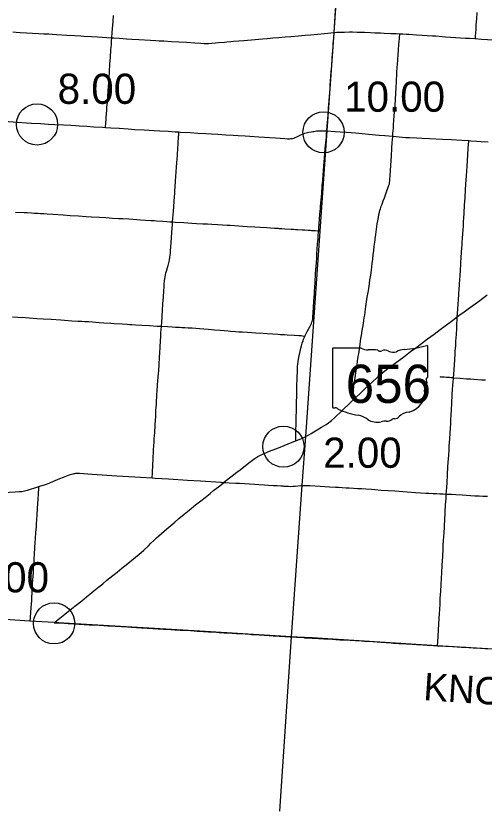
# Model space of a CAD drawing. Extents: x 1813937 to 1948437, y 826606 to 1022856.
# Drawn here: x 1890191 to 1907255, y 849557 to 878544 of the extents above; entities that cross this region are included whole.
import ezdxf

# ---------------------------------------------------------------- set-up
doc = ezdxf.new("R2010")
doc.units = 0
for name, color, linetype in [('Default', 7, 'Continuous'), ('GM_X_Adjacent_County', 7, 'Continuous'), ('GM_X_Adjacent_County_Text', 7, 'Continuous'), ('GM_X_County', 7, 'Continuous'), ('GM_X_County_Road', 7, 'Continuous'), ('GM_X_State_Route', 7, 'Continuous'), ('GM_X_State_Shield', 7, 'Continuous'), ('GM_X_Township', 7, 'Continuous'), ('GM_X_Township_Road', 7, 'Continuous')]:
    doc.layers.add(name, color=color, linetype=linetype)

msp = doc.modelspace()

# ---------------------------------------------------------------- linework, layer by layer
at = {"layer": 'Default'}
for centre in [(1890962, 874588), (1901403, 874300), (1899943, 862842), (1891585, 856400)]:
    msp.add_circle(centre, 750, dxfattribs=at)
at = {"layer": 'GM_X_Adjacent_County'}
msp.add_line((1900228, 855908), (1899800, 849557), dxfattribs=at)
at = {"layer": 'GM_X_County'}
msp.add_lwpolyline([(1909640, 855342), (1905546, 855583), (1900992, 855867), (1900447, 855895), (1900228, 855908), (1896895, 856116), (1891937, 856405), (1891588, 856432), (1890695, 856480), (1886895, 856734)], dxfattribs=at)
at = {"layer": 'GM_X_County_Road'}
for points in [[(1901788, 877939), (1901801, 878159), (1901811, 878322), (1901825, 878552), (1901847, 878896), (1901869, 879256), (1901894, 879616), (1901903, 879780), (1901914, 879927), (1901928, 880124), (1901938, 880255), (1901953, 880500), (1901979, 880877), (1901991, 881073), (1902003, 881270), (1902016, 881499), (1902024, 881630), (1902038, 881827), (1902052, 882023), (1902064, 882205)], [(1901526, 874352), (1901541, 874540), (1901560, 874771), (1901575, 874967), (1901585, 875124), (1901590, 875197), (1901597, 875311), (1901620, 875605), (1901640, 875884), (1901650, 876015), (1901672, 876326), (1901686, 876522), (1901701, 876718), (1901721, 876997), (1901743, 877291), (1901752, 877406), (1901760, 877537), (1901773, 877733), (1901788, 877939)], [(1906279, 867576), (1906289, 867687), (1906301, 867867), (1906324, 868201), (1906336, 868382), (1906351, 868620), (1906357, 868701), (1906361, 868767), (1906372, 868930), (1906382, 869077), (1906392, 869258), (1906397, 869339), (1906403, 869437), (1906409, 869536), (1906424, 869748), (1906435, 869912), (1906448, 870108), (1906452, 870174), (1906461, 870304), (1906470, 870435), (1906482, 870615), (1906491, 870746), (1906500, 870893), (1906508, 871057), (1906514, 871155), (1906524, 871368), (1906542, 871647), (1906561, 871908), (1906582, 872219), (1906606, 872579), (1906614, 872694), (1906628, 872906), (1906638, 873054), (1906653, 873283), (1906665, 873463), (1906679, 873725), (1906688, 873859), (1906695, 873970), (1906696, 873998)], [(1906139, 865355), (1906148, 865479), (1906161, 865659), (1906173, 865815), (1906185, 866019), (1906199, 866231), (1906205, 866329), (1906219, 866526), (1906230, 866675), (1906238, 866822), (1906244, 866918), (1906256, 867164), (1906266, 867327), (1906272, 867458), (1906276, 867540), (1906279, 867576)], [(1905878, 861113), (1905895, 861355), (1905906, 861535), (1905921, 861797), (1905939, 862119), (1905957, 862403), (1905965, 862534), (1905977, 862730), (1905986, 862861), (1905993, 862992), (1906002, 863123), (1906029, 863532), (1906038, 863679), (1906046, 863827), (1906056, 864007), (1906068, 864187), (1906081, 864432), (1906084, 864514), (1906092, 864645), (1906097, 864743), (1906108, 864923), (1906119, 865070), (1906129, 865201), (1906138, 865332), (1906139, 865355)], [(1891033, 861391), (1891103, 861412), (1891228, 861451), (1891306, 861477), (1891367, 861499), (1891427, 861524), (1891533, 861569), (1891790, 861677), (1891927, 861733), (1892050, 861779), (1892174, 861823), (1892221, 861838), (1892284, 861856), (1892317, 861863), (1892340, 861867), (1892376, 861873), (1892414, 861874), (1892457, 861874), (1892511, 861873), (1892657, 861863), (1892975, 861844), (1893875, 861784), (1894530, 861742), (1894727, 861729), (1895156, 861701)], [(1895156, 861701), (1895267, 861694), (1895758, 861664), (1896445, 861620), (1896920, 861591), (1897657, 861542), (1897691, 861539), (1897763, 861534)], [(1897763, 861534), (1897839, 861530), (1897960, 861524), (1898208, 861515), (1898338, 861507), (1898526, 861493), (1898704, 861483), (1898895, 861472), (1899045, 861464), (1899246, 861452), (1899400, 861441), (1899581, 861430), (1899712, 861422), (1899842, 861413), (1899917, 861408)], [(1889657, 861171), (1889692, 861173), (1889953, 861185), (1890166, 861196), (1890328, 861205), (1890402, 861211), (1890451, 861216), (1890507, 861229), (1890555, 861240), (1890618, 861258), (1890993, 861378), (1891033, 861391)], [(1899917, 861408), (1899957, 861406), (1900023, 861403), (1900085, 861399)], [(1900085, 861399), (1900121, 861397), (1900203, 861395), (1900285, 861397), (1900367, 861402), (1900580, 861425), (1900581, 861425)], [(1900581, 861425), (1900655, 861430), (1900723, 861431), (1900792, 861429), (1900906, 861425), (1901275, 861404), (1901620, 861382), (1901838, 861371), (1901949, 861365), (1902082, 861356), (1902229, 861346), (1902336, 861340), (1902491, 861330), (1902642, 861318), (1902782, 861311), (1902943, 861304), (1903156, 861289), (1903274, 861276), (1903498, 861259), (1903761, 861241), (1903998, 861229), (1904157, 861221), (1904294, 861213), (1904450, 861200), (1904752, 861174), (1904940, 861161), (1905132, 861150), (1905237, 861146), (1905393, 861139), (1905528, 861131), (1905646, 861126), (1905759, 861120), (1905878, 861113)], [(1905558, 855587), (1905569, 855740), (1905581, 855920), (1905607, 856378), (1905629, 856755), (1905638, 856902), (1905649, 857098), (1905659, 857311), (1905673, 857573), (1905685, 857803), (1905701, 858048), (1905712, 858247), (1905728, 858523), (1905746, 858834), (1905761, 859112), (1905769, 859243), (1905779, 859424), (1905789, 859571), (1905796, 859718), (1905807, 859898), (1905828, 860242), (1905835, 860356), (1905841, 860471), (1905854, 860717), (1905867, 860946), (1905878, 861110), (1905878, 861113)], [(1905878, 861113), (1905907, 861112), (1906070, 861106), (1906219, 861099), (1906460, 861085), (1906607, 861075), (1906762, 861065), (1906918, 861053), (1907080, 861046), (1907206, 861041), (1907376, 861036)], [(1891583, 856425), (1891639, 856423), (1891746, 856417), (1891965, 856405)], [(1891965, 856405), (1892090, 856398), (1892301, 856385), (1892481, 856374), (1892856, 856351), (1893019, 856342), (1893232, 856329), (1893543, 856312), (1893805, 856297), (1893879, 856293), (1894034, 856284), (1894263, 856272), (1894410, 856264), (1894495, 856259)], [(1894495, 856259), (1894590, 856253), (1894770, 856241), (1894983, 856228), (1895376, 856205), (1895572, 856194), (1895703, 856186), (1895981, 856169), (1896095, 856161), (1896177, 856156), (1896242, 856153), (1896308, 856149), (1896553, 856136), (1896684, 856128), (1896799, 856122), (1896913, 856115), (1896923, 856115)], [(1896923, 856115), (1897028, 856108), (1897142, 856101), (1897208, 856097), (1897503, 856079), (1897601, 856072), (1897699, 856066), (1897780, 856061), (1897911, 856054), (1898222, 856035), (1898370, 856027), (1898550, 856015), (1898713, 856004), (1898778, 856000), (1898893, 855993), (1899057, 855983), (1899416, 855960), (1899563, 855950), (1899678, 855942), (1899792, 855935), (1899988, 855922), (1900186, 855910)], [(1900186, 855910), (1900418, 855898), (1900516, 855892), (1900679, 855880), (1900711, 855878), (1900792, 855875), (1900873, 855872), (1900987, 855865), (1901117, 855858), (1901216, 855852), (1901412, 855841), (1901477, 855838), (1901559, 855834), (1901730, 855823), (1901855, 855815), (1902001, 855805), (1902166, 855796), (1902566, 855776), (1902784, 855762), (1902899, 855755), (1903029, 855748), (1903195, 855737), (1903359, 855726), (1903490, 855716), (1903572, 855710), (1903686, 855702), (1903866, 855689), (1903948, 855683), (1904151, 855671), (1904291, 855661), (1904422, 855654), (1904635, 855643), (1904787, 855633), (1904900, 855626), (1905019, 855619), (1905109, 855614), (1905174, 855610), (1905275, 855603), (1905405, 855595), (1905488, 855590), (1905558, 855587)]]:
    msp.add_lwpolyline(points, dxfattribs=at)
at = {"layer": 'GM_X_State_Route'}
for points in [[(1889758, 874704), (1890249, 874670), (1890576, 874650), (1890756, 874639), (1891084, 874620), (1891379, 874602), (1891608, 874588), (1891936, 874570), (1892198, 874556), (1892362, 874545), (1892493, 874537), (1892771, 874520), (1893033, 874504), (1893344, 874485), (1893457, 874478), (1893655, 874466), (1893950, 874446), (1894278, 874425), (1894523, 874409), (1894867, 874390), (1895227, 874371), (1895440, 874359), (1895735, 874340), (1895999, 874324), (1896130, 874316), (1896194, 874311), (1896545, 874289), (1896816, 874273), (1897111, 874256), (1897318, 874243), (1897553, 874228), (1897848, 874210), (1898110, 874195), (1898295, 874184), (1898552, 874168), (1898716, 874157), (1899043, 874137), (1899649, 874101), (1899993, 874075), (1900091, 874069), (1900157, 874068), (1900207, 874070), (1900240, 874073), (1900272, 874079), (1900320, 874091), (1900367, 874108), (1900428, 874133), (1900576, 874203), (1900666, 874244), (1900727, 874268), (1900773, 874283), (1900820, 874296), (1900868, 874306), (1900948, 874320), (1901007, 874330), (1901046, 874336), (1901092, 874342), (1901155, 874349), (1901230, 874356), (1901307, 874358), (1901372, 874358), (1901479, 874355), (1901526, 874352), (1901827, 874333), (1902007, 874320), (1902236, 874305), (1902416, 874291), (1902563, 874278), (1902808, 874257), (1903037, 874237), (1903429, 874202), (1903641, 874181), (1903918, 874156), (1903926, 874155), (1904277, 874122), (1904408, 874113), (1904539, 874106), (1904801, 874094), (1904997, 874087), (1905259, 874074), (1905735, 874054), (1906062, 874039), (1906439, 874017), (1906696, 873998), (1906766, 873993), (1906995, 873980), (1907143, 873972), (1907404, 873956)], [(1891583, 856425), (1891666, 856492), (1891977, 856734), (1892233, 856938), (1892386, 857062), (1892590, 857227), (1892769, 857371), (1892883, 857465), (1893036, 857588), (1893214, 857733), (1893354, 857847), (1893507, 857970), (1893725, 858144), (1893878, 858268), (1894056, 858412), (1894208, 858537), (1894474, 858756), (1894751, 858988), (1894850, 859074), (1895018, 859229), (1895114, 859320), (1895219, 859423), (1895313, 859515), (1895397, 859593), (1895495, 859680), (1895694, 859850), (1895983, 860092), (1896133, 860220), (1896321, 860378), (1896502, 860529), (1896742, 860718), (1896934, 860871), (1897088, 860994), (1897266, 861138), (1897408, 861250), (1897574, 861383), (1897740, 861517), (1897763, 861534), (1897869, 861618), (1898025, 861739), (1898243, 861912), (1898360, 862002), (1898683, 862253), (1898814, 862353), (1898880, 862401), (1898934, 862437), (1899004, 862479), (1899076, 862519), (1899149, 862555), (1899239, 862595), (1899436, 862676), (1899665, 862767), (1899878, 862851), (1900198, 862977), (1900351, 863038), (1900389, 863053), (1900536, 863112), (1900631, 863153), (1900707, 863188), (1900715, 863192), (1900793, 863231), (1900864, 863272), (1900956, 863324), (1901044, 863377), (1901174, 863454), (1901326, 863549), (1901497, 863655), (1901582, 863713), (1901644, 863757), (1901696, 863800), (1901806, 863898), (1902080, 864158), (1902377, 864442), (1902555, 864611), (1902581, 864636), (1902759, 864802), (1902926, 864957), (1903205, 865215), (1903322, 865323), (1903470, 865459), (1903569, 865546), (1903638, 865602), (1903736, 865683), (1903878, 865788), (1904009, 865886), (1904326, 866120), (1904577, 866305), (1904761, 866443), (1904971, 866600), (1905195, 866767), (1905433, 866942), (1905656, 867109), (1905788, 867207), (1906115, 867454), (1906279, 867576), (1906339, 867621), (1906525, 867756), (1906671, 867862), (1907094, 868173), (1907371, 868378)]]:
    msp.add_lwpolyline(points, dxfattribs=at)
at = {"layer": 'GM_X_State_Shield'}
for p, q in [((1902780, 866438), (1901761, 866438)), ((1905207, 865385), (1905207, 866490)), ((1901727, 866402), (1901727, 864288)), ((1905207, 865385), (1905207, 865385))]:
    msp.add_line(p, q, dxfattribs=at)
for centre, major_axis, start_param, end_param in [((1901767, 866406), (40.3, 0), 1.712693, 3.28349), ((1903023, 866683), (391, 0), 4.042523, 4.731795), ((1903967, 869319), (3691, 0), 4.814394, 5.042369), ((1905168, 866495), (38.7, 0), 6.141152, 7.989035), ((1903153, 865252), (1404, 0), 1.404758, 1.657858), ((1903471, 866417), (113, 0), 3.836095, 5.185415), ((1903637, 866173), (235, 0), 0.950623, 2.079405), ((1903940, 866508), (282, 0), 4.081561, 5.145723), ((1904438, 865793), (743, 0), 1.699011, 2.107814), ((1905198, 865304), (60, 0), 1.883978, 3.671073), ((1904817, 865164), (360, 0), 5.934695, 6.695948), ((1905166, 865381), (41.5, 0), 5.05454, 6.418171), ((1905346, 864922), (262, 0), 2.387724, 3.262537), ((1904174, 864782), (923, 0), 5.101752, 6.440018), ((1901767, 864284), (40.7, 0), 3.00124, 4.508301), ((1901773, 864500), (310, 0), 4.665946, 4.897461), ((1901837, 864167), (112, 0), 0.519207, 1.627899), ((1903250, 866065), (2665, 0), 4.195997, 4.488961), ((1902455, 863339), (834, 0), 0.823519, 1.323587), ((1903357, 864156), (529, 0), 4.026481, 4.996735), ((1903702, 863998), (282, 0), 4.691044, 5.507374), ((1903957, 863793), (79.4, 0), 1.147584, 2.315152), ((1903923, 864084), (298, 0), 4.937069, 5.64225), ((1904563, 863695), (506, 0), 1.647645, 2.488434), ((1903663, 863425), (435, 0), 1.495662, 1.94098)]:
    msp.add_ellipse(centre, major_axis=major_axis, ratio=0.8, start_param=start_param, end_param=end_param, dxfattribs=at)
at = {"layer": 'GM_X_Township'}
msp.add_lwpolyline([(1888679, 882953), (1894036, 882664), (1902065, 882212), (1901776, 877944), (1901523, 874357), (1900741, 863210), (1900616, 861438), (1900228, 855908)], dxfattribs=at)
at = {"layer": 'GM_X_Township_Road'}
for points in [[(1906935, 877716), (1906936, 877737), (1906944, 877818), (1906952, 877917), (1906962, 878064), (1906971, 878212), (1906979, 878343), (1906985, 878424), (1906998, 878670)], [(1893689, 877747), (1893702, 877943), (1893722, 878205), (1893730, 878335), (1893745, 878564)], [(1890083, 877958), (1890202, 877951), (1890348, 877942), (1890573, 877932), (1890802, 877920), (1891015, 877908), (1891211, 877896), (1891300, 877891), (1891394, 877886), (1891514, 877878), (1891670, 877870), (1892046, 877846), (1892325, 877828), (1892554, 877814), (1892669, 877807), (1892947, 877790), (1893160, 877777), (1893340, 877766), (1893504, 877758), (1893689, 877747)], [(1893457, 874478), (1893459, 874511), (1893467, 874609), (1893482, 874821), (1893497, 875001), (1893502, 875083), (1893511, 875213), (1893524, 875393), (1893539, 875606), (1893554, 875818), (1893573, 876113), (1893586, 876292), (1893599, 876505), (1893619, 876799), (1893636, 877028), (1893655, 877306), (1893672, 877502), (1893681, 877633), (1893689, 877747)], [(1893689, 877747), (1893764, 877742), (1893962, 877731), (1894224, 877713), (1894421, 877700), (1894666, 877685), (1895092, 877658), (1895289, 877648), (1895410, 877641), (1895583, 877632), (1895862, 877617), (1896124, 877602), (1896403, 877585), (1896714, 877565), (1896927, 877552), (1897058, 877544), (1897156, 877542), (1897205, 877542), (1897336, 877551), (1897467, 877561), (1897581, 877569), (1897794, 877588), (1897875, 877596), (1898022, 877609), (1898120, 877618), (1898316, 877636), (1898496, 877653), (1898627, 877664), (1898774, 877675), (1899183, 877708), (1899347, 877721), (1899461, 877731), (1899559, 877740), (1899772, 877758), (1900000, 877777), (1900213, 877795), (1900491, 877819), (1900736, 877841), (1900932, 877858), (1901177, 877881), (1901439, 877905), (1901668, 877926), (1901788, 877939)], [(1901788, 877939), (1901890, 877947), (1901955, 877950), (1902168, 877955), (1902349, 877960), (1902464, 877960), (1902628, 877957), (1902759, 877952), (1902890, 877946), (1903119, 877938), (1903267, 877932), (1903381, 877928), (1903480, 877924), (1903611, 877918), (1903873, 877907), (1904053, 877899), (1904181, 877893)], [(1904132, 877278), (1904134, 877308), (1904153, 877504), (1904160, 877603), (1904169, 877717), (1904176, 877799), (1904179, 877848), (1904181, 877893)], [(1904181, 877893), (1904201, 877892), (1904299, 877888), (1904430, 877881), (1904512, 877877), (1904659, 877867), (1904790, 877859), (1905003, 877844), (1905183, 877832), (1905379, 877820), (1905494, 877813), (1905854, 877787), (1906214, 877763), (1906574, 877738), (1906721, 877728), (1906918, 877717), (1906935, 877716)], [(1906935, 877716), (1907164, 877701), (1907376, 877688), (1907671, 877669), (1907900, 877654), (1908195, 877633), (1908342, 877624)], [(1903926, 874155), (1903934, 874260), (1903947, 874457), (1903957, 874588), (1903969, 874735), (1903982, 874899), (1903993, 875030), (1903998, 875095), (1904015, 875308), (1904026, 875488), (1904038, 875734), (1904046, 875898), (1904062, 876193), (1904072, 876407), (1904077, 876489), (1904089, 876669), (1904096, 876784), (1904106, 876931), (1904121, 877145), (1904132, 877278)], [(1895904, 871035), (1895904, 871044), (1895914, 871175), (1895931, 871420), (1895959, 871780), (1895972, 871960), (1895978, 872059), (1895987, 872190), (1895995, 872304), (1896011, 872534), (1896021, 872681), (1896034, 872878), (1896045, 873018), (1896058, 873201), (1896066, 873320), (1896076, 873467), (1896081, 873549), (1896087, 873647), (1896106, 873942), (1896114, 874085), (1896125, 874242), (1896130, 874316)], [(1901228, 870711), (1901236, 870824), (1901247, 870972), (1901259, 871136), (1901273, 871316), (1901282, 871430), (1901289, 871511), (1901297, 871609), (1901315, 871822), (1901335, 872084), (1901356, 872345), (1901372, 872558), (1901387, 872738), (1901415, 873081), (1901440, 873359), (1901454, 873539), (1901467, 873719), (1901485, 873915), (1901505, 874128), (1901517, 874258), (1901526, 874352)], [(1902581, 864636), (1902566, 864657), (1902529, 864711), (1902511, 864739), (1902504, 864753), (1902498, 864769), (1902494, 864784), (1902491, 864801), (1902489, 864817), (1902489, 864850), (1902493, 864899), (1902510, 865029), (1902525, 865143), (1902543, 865272), (1902554, 865354), (1902566, 865435), (1902584, 865548), (1902602, 865661), (1902629, 865839), (1902645, 865953), (1902671, 866132), (1902686, 866229), (1902710, 866391), (1902738, 866569), (1902755, 866682), (1902768, 866780), (1902785, 866893), (1902816, 867071), (1902839, 867200), (1902859, 867330), (1902876, 867443), (1902889, 867541), (1902903, 867638), (1902920, 867752), (1902948, 867946), (1902973, 868125), (1902998, 868287), (1903027, 868465), (1903048, 868611), (1903061, 868692), (1903076, 868789), (1903095, 868919), (1903122, 869097), (1903147, 869276), (1903179, 869519), (1903200, 869682), (1903217, 869829), (1903235, 869992), (1903253, 870154), (1903270, 870301), (1903279, 870366), (1903285, 870414), (1903305, 870577), (1903318, 870674), (1903346, 870869), (1903361, 870966), (1903382, 871079), (1903403, 871191), (1903423, 871304), (1903440, 871384), (1903457, 871448), (1903477, 871510), (1903508, 871603), (1903535, 871681), (1903579, 871804), (1903620, 871911), (1903688, 872096), (1903762, 872296), (1903788, 872374), (1903802, 872421), (1903812, 872469), (1903819, 872518), (1903825, 872583), (1903836, 872730), (1903845, 872894), (1903859, 873107), (1903879, 873434), (1903897, 873729), (1903909, 873925), (1903916, 874023), (1903925, 874145), (1903926, 874155)], [(1890175, 871396), (1890487, 871382), (1890601, 871375), (1890757, 871365), (1890873, 871356), (1890990, 871349), (1891091, 871343), (1891207, 871337), (1891336, 871329), (1891534, 871317), (1891911, 871290), (1892173, 871273), (1892467, 871254), (1892746, 871236), (1892942, 871224), (1893237, 871205), (1893468, 871191), (1893712, 871176), (1893925, 871165), (1894089, 871155), (1894302, 871142), (1894449, 871133), (1894596, 871123), (1894727, 871114), (1894917, 871101), (1895106, 871089), (1895235, 871081), (1895317, 871076), (1895547, 871061), (1895693, 871050), (1895807, 871042), (1895857, 871039), (1895895, 871036), (1895904, 871035)], [(1895496, 867229), (1895507, 867386), (1895534, 867804), (1895549, 868044), (1895567, 868303), (1895581, 868515), (1895591, 868679), (1895597, 868761), (1895609, 868892), (1895619, 868973), (1895629, 869038), (1895641, 869102), (1895660, 869181), (1895678, 869244), (1895718, 869369), (1895740, 869448), (1895764, 869543), (1895785, 869640), (1895806, 869752), (1895815, 869817), (1895824, 869898), (1895830, 869996), (1895839, 870127), (1895851, 870274), (1895867, 870482), (1895878, 870634), (1895891, 870814), (1895898, 870929), (1895904, 871035)], [(1895904, 871035), (1896000, 871029), (1896311, 871010), (1896605, 870991), (1896769, 870982), (1896998, 870970), (1897179, 870960), (1897326, 870950), (1897545, 870938), (1897726, 870926), (1897886, 870916), (1897997, 870910), (1898161, 870900), (1898619, 870873), (1898898, 870854), (1899094, 870842), (1899340, 870827), (1899471, 870819), (1899618, 870810), (1899749, 870802), (1899781, 870799), (1899879, 870794), (1899994, 870787), (1900223, 870774), (1900305, 870768), (1900387, 870763), (1900469, 870758), (1900632, 870746), (1900725, 870741), (1900838, 870734), (1900913, 870730), (1900966, 870727), (1901018, 870725), (1901092, 870719), (1901214, 870712), (1901228, 870711)], [(1901071, 868478), (1901073, 868517), (1901081, 868648), (1901093, 868828), (1901116, 869172), (1901131, 869401), (1901144, 869565), (1901154, 869712), (1901164, 869876), (1901175, 870040), (1901188, 870236), (1901202, 870400), (1901213, 870531), (1901225, 870678), (1901228, 870711)], [(1900721, 866865), (1900749, 866921), (1900810, 867037), (1900900, 867212), (1900959, 867329), (1900978, 867375), (1900988, 867406), (1900999, 867454), (1901007, 867502), (1901011, 867551), (1901022, 867732), (1901034, 867912), (1901050, 868141), (1901068, 868419), (1901071, 868478)], [(1890073, 867578), (1890264, 867565), (1890542, 867546), (1890952, 867519), (1891186, 867504), (1891475, 867484), (1891832, 867461), (1892228, 867433), (1892458, 867420), (1892589, 867412), (1892703, 867406), (1892834, 867399), (1892982, 867389), (1893223, 867373), (1893391, 867361), (1893653, 867344), (1893767, 867337), (1894062, 867318), (1894242, 867307), (1894341, 867301), (1894421, 867295), (1894550, 867288), (1894779, 867274), (1895057, 867256), (1895336, 867238), (1895496, 867229)], [(1895156, 861701), (1895158, 861724), (1895168, 861855), (1895185, 862232), (1895189, 862351), (1895195, 862496), (1895202, 862591), (1895209, 862710), (1895218, 862885), (1895227, 863003), (1895235, 863130), (1895243, 863246), (1895249, 863343), (1895256, 863425), (1895262, 863539), (1895270, 863678), (1895278, 863788), (1895287, 863954), (1895297, 864164), (1895304, 864283), (1895311, 864397), (1895316, 864469), (1895318, 864537), (1895322, 864628), (1895325, 864684), (1895329, 864750), (1895335, 864851), (1895354, 865098), (1895364, 865238), (1895377, 865377), (1895389, 865514), (1895398, 865612), (1895413, 865841), (1895430, 866102), (1895437, 866258), (1895448, 866453), (1895465, 866708), (1895472, 866850), (1895479, 866996), (1895486, 867110), (1895494, 867214), (1895496, 867229)], [(1895496, 867229), (1895720, 867217), (1895883, 867207), (1896013, 867200), (1896154, 867193), (1896234, 867191), (1896351, 867186), (1896468, 867179), (1896614, 867169), (1896746, 867158), (1896878, 867147), (1897038, 867134), (1897201, 867121), (1897316, 867112), (1897430, 867104), (1897630, 867088), (1897779, 867075), (1897928, 867063), (1898017, 867055), (1898199, 867040), (1898319, 867032), (1898445, 867024), (1898632, 867011), (1898940, 866993), (1899197, 866975), (1899345, 866966), (1899557, 866952), (1899754, 866940), (1899836, 866935), (1899983, 866926), (1900081, 866921), (1900327, 866907), (1900507, 866895), (1900589, 866888), (1900637, 866882), (1900686, 866872), (1900721, 866865)], [(1900389, 863053), (1900390, 863142), (1900391, 863289), (1900396, 863453), (1900401, 863650), (1900406, 863847), (1900414, 864224), (1900421, 864486), (1900425, 864667), (1900425, 864749), (1900428, 864864), (1900435, 865091), (1900440, 865290), (1900453, 865667), (1900458, 865782), (1900464, 865847), (1900477, 865945), (1900490, 866026), (1900514, 866155), (1900549, 866315), (1900575, 866427), (1900601, 866522), (1900629, 866618), (1900655, 866698), (1900678, 866761), (1900699, 866812), (1900720, 866862), (1900721, 866865)], [(1905640, 865396), (1905666, 865393)], [(1905666, 865393), (1905673, 865392), (1905700, 865389), (1905737, 865387), (1905799, 865383), (1905889, 865377), (1905948, 865374), (1905998, 865370), (1906052, 865364), (1906081, 865362), (1906103, 865360), (1906121, 865358), (1906131, 865356), (1906139, 865355)], [(1906139, 865355), (1906388, 865333), (1906617, 865318), (1906764, 865309), (1906878, 865302), (1907155, 865282), (1907302, 865272)], [(1890717, 856500), (1890716, 856519), (1890717, 856546), (1890718, 856566), (1890722, 856632), (1890734, 856796), (1890747, 856976), (1890766, 857238), (1890789, 857631), (1890802, 857860), (1890819, 858106), (1890829, 858270), (1890835, 858384), (1890845, 858531), (1890854, 858662), (1890860, 858760), (1890870, 858907), (1890886, 859169), (1890897, 859348), (1890909, 859495), (1890922, 859708), (1890936, 859920), (1890941, 860018), (1890952, 860182), (1890964, 860362), (1890977, 860591), (1891001, 860935), (1891012, 861116), (1891029, 861345), (1891032, 861382), (1891033, 861391)], [(1905558, 855587), (1905695, 855578), (1905859, 855569), (1906104, 855555), (1906437, 855537), (1906585, 855530), (1906699, 855525), (1906856, 855514), (1906960, 855507), (1907282, 855488), (1907610, 855470), (1907839, 855457), (1908019, 855447), (1908182, 855436), (1908297, 855429), (1908559, 855411), (1908689, 855403), (1908804, 855396), (1908984, 855385), (1909229, 855370), (1909474, 855353), (1909637, 855341), (1909654, 855341)]]:
    msp.add_lwpolyline(points, dxfattribs=at)

# ---------------------------------------------------------------- texts
at = {"layer": 'Default'}
for s, p in [('8.00', (1891712, 875338)), ('10.00', (1902153, 875050)), ('2.00', (1901390, 862072)), ('0.00', (1888535, 857530))]:
    msp.add_text(s, height=1100, dxfattribs=at).set_placement(p)
at = {"layer": 'GM_X_Adjacent_County_Text'}
msp.add_text('KNOX COUNTY', height=1000, rotation=356.2231, dxfattribs=at).set_placement((1905024, 853603))
at = {"layer": 'GM_X_State_Shield'}
msp.add_text('656', height=1392.2, dxfattribs=at).set_placement((1902212, 864437))

doc.saveas('drawing.dxf')
